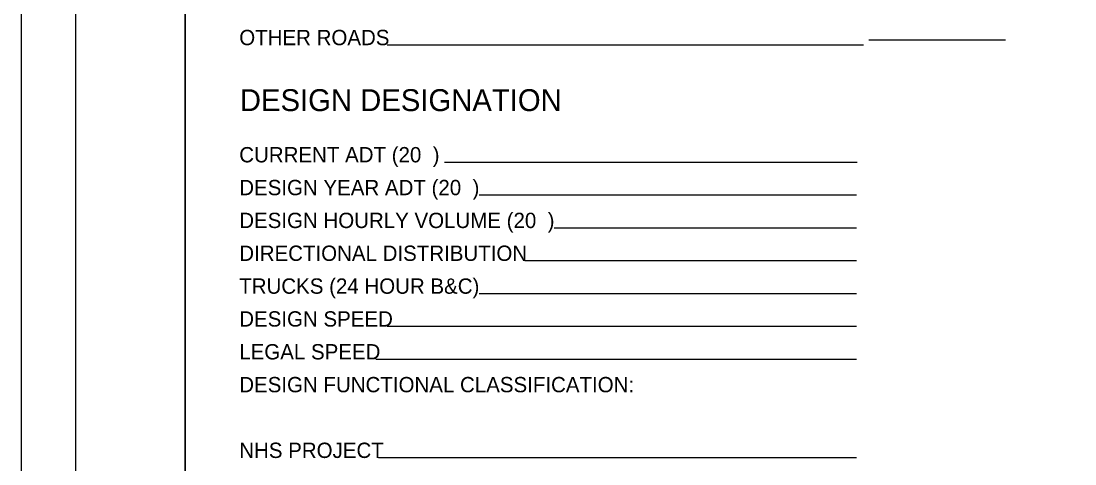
# Model space of a CAD drawing. Extents: x 0 to 44, y -23.8 to 22.
# Drawn here: x 10.02 to 19.66, y -16.73 to -12.69 of the extents above; entities that cross this region are included whole.
import ezdxf

# ---------------------------------------------------------------- set-up
doc = ezdxf.new("R2010")
doc.units = 0
for name, color, linetype in [('SH_Border', 7, 'Continuous'), ('SH_Cut_Line', 7, 'Continuous'), ('SH_Data', 7, 'Continuous'), ('SH_Text', 7, 'Continuous')]:
    doc.layers.add(name, color=color, linetype=linetype)

msp = doc.modelspace()

# ---------------------------------------------------------------- linework, layer by layer
at = {"layer": 'SH_Border'}
for points in [[(10.5245, -2.2855), (11.5245, -2.2855), (11.5245, -23.2855), (10.5245, -23.2855)], [(11.5245, -2.2855), (43.5245, -2.2855), (43.5245, -23.2855), (11.5245, -23.2855)]]:
    msp.add_lwpolyline(points, close=True, dxfattribs=at)
at = {"layer": 'SH_Cut_Line'}
msp.add_lwpolyline([(10.0245, -23.7855), (44.0245, -23.7855), (44.0245, -1.7855), (10.0245, -1.7855)], close=True, dxfattribs=at)
at = {"layer": 'SH_Data'}
for p, q in [((19.0245, -12.8632), (17.7745, -12.8632)), ((17.7245, -12.9088), (13.3716, -12.9088)), ((17.6669, -13.9792), (13.8955, -13.9792)), ((17.6614, -14.2792), (14.213, -14.2792)), ((17.6614, -14.5792), (14.8968, -14.5792)), ((17.6614, -14.8792), (14.6282, -14.8792)), ((17.6614, -15.1792), (14.213, -15.1792)), ((17.6614, -15.4792), (13.3705, -15.4792)), ((17.6614, -15.7792), (13.2667, -15.7792)), ((17.6614, -16.6792), (13.2914, -16.6792))]:
    msp.add_line(p, q, dxfattribs=at)

# ---------------------------------------------------------------- texts
msp.add_text('DESIGN DESIGNATION', height=0.2, dxfattribs=at).set_placement((12.0245, -13.5108))
at = {"layer": 'SH_Text'}
for s, p in [('OTHER ROADS', (12.0189, -12.9088)), ('CURRENT ADT (20  )', (12.0189, -13.9792)), ('DESIGN YEAR ADT (20  )', (12.0189, -14.2792)), ('DESIGN HOURLY VOLUME (20  )', (12.0189, -14.5792)), ('DIRECTIONAL DISTRIBUTION', (12.0189, -14.8792)), ('TRUCKS (24 HOUR B&C)', (12.0189, -15.1792)), ('DESIGN SPEED', (12.0189, -15.4792)), ('LEGAL SPEED', (12.0189, -15.7792)), ('DESIGN FUNCTIONAL CLASSIFICATION:', (12.0189, -16.0792)), ('NHS PROJECT', (12.0189, -16.6792))]:
    msp.add_text(s, height=0.14, dxfattribs=at).set_placement(p)

doc.saveas('drawing.dxf')
